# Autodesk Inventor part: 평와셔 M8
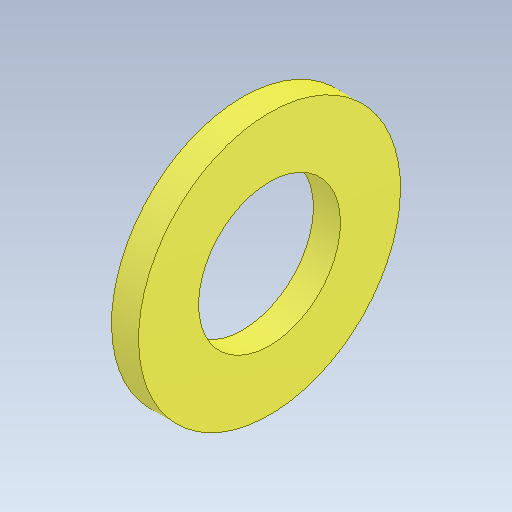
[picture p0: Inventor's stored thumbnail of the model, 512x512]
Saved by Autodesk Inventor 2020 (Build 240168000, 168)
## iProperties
Created: 2024-04
Part Number: 평와셔 M8
Material: 강철, 연강
Description: 평면 와셔
Document SubType Name: Modeling
Designer: oem
Density: 7.86 g/cm^3
Appearance: 기본값
Mass: 1.67606 g
Surface Area: 3.86683 cm^2
Volume: 0.213239 cm^3
Sending System: Autodesk Inventor 2025
Preprocessor: ST-DEVELOPER v20
Author: jhkim
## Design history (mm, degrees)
feature "Solid1"
node "솔리드1"
